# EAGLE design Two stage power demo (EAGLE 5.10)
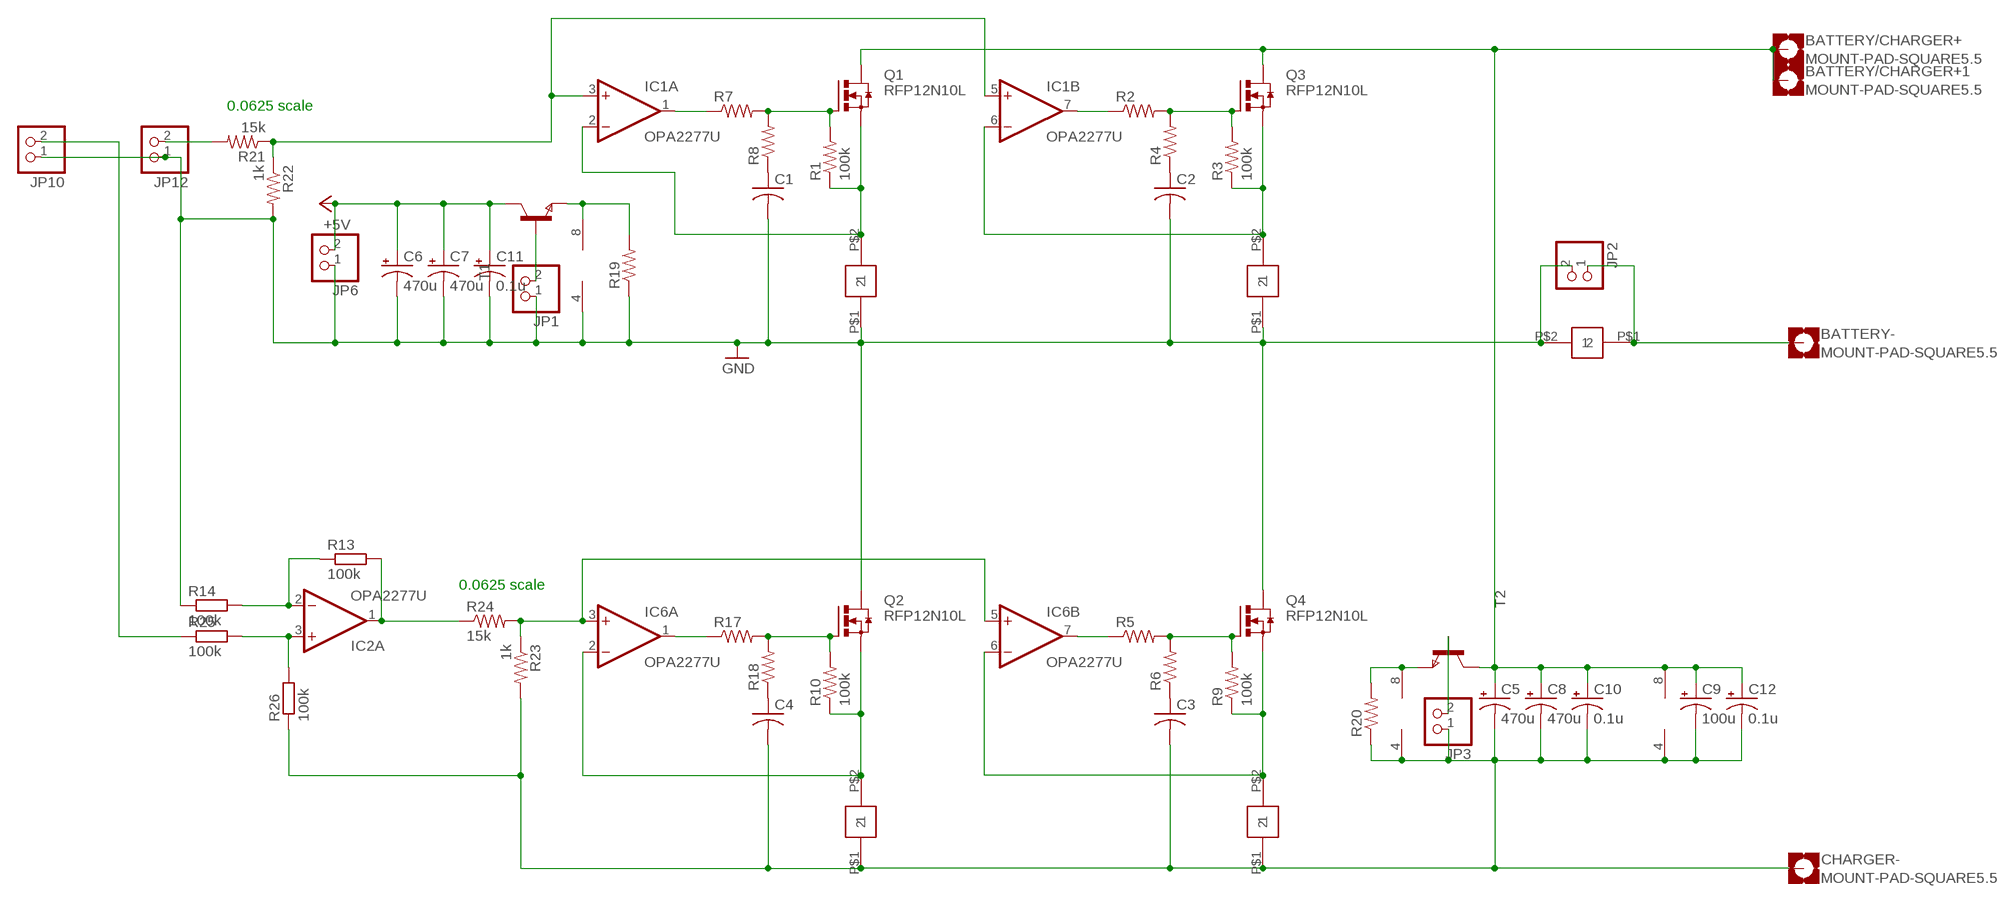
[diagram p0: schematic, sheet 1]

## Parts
1  630HR050E  [630HR050E]
BATTERY-  MOUNT-PAD-SQUARE5.5  [5,5-PAD-SQUARE]
BATTERY/CHARGER+  MOUNT-PAD-SQUARE5.5  [5,5-PAD-SQUARE]
BATTERY/CHARGER+1  MOUNT-PAD-SQUARE5.5  [5,5-PAD-SQUARE]
C1  C-US150-054X183  [C150-054X183]
C2  C-US150-054X183  [C150-054X183]
C3  C-US150-054X183  [C150-054X183]
C4  C-US150-054X183  [C150-054X183]
C5  470u  CPOL-USE5-10.5  [E5-10,5]
C6  470u  CPOL-USE5-10.5  [E5-10,5]
C7  470u  CPOL-USE5-10.5  [E5-10,5]
C8  470u  CPOL-USE5-10.5  [E5-10,5]
C9  100u  CPOL-USE2.5-7  [E2,5-7]
C10  0.1u  CPOL-USE2-4  [E2-4]
C11  0.1u  CPOL-USE2-4  [E2-4]
C12  0.1u  CPOL-USE2-4  [E2-4]
CHARGER-  MOUNT-PAD-SQUARE5.5  [5,5-PAD-SQUARE]
IC1  OPA2277U  [SO08]
IC2  OPA2277U  [SO08]
IC6  OPA2277U  [SO08]
JP1  PINHD-1X2  [1X02]
JP2  PINHD-1X2  [1X02]
JP3  PINHD-1X2  [1X02]
JP6  PINHD-1X2  [1X02]
JP10  PINHD-1X2  [1X02]
JP12  PINHD-1X2  [1X02]
Q1  RFP12N10L  [TO220-W/657-20ABP]
Q2  RFP12N10L  [TO220-W/657-20ABP]
Q3  RFP12N10L  [TO220-W/657-20ABP]
Q4  RFP12N10L  [TO220-W/657-20ABP]
R1  100k  R-US_0411/12  [0411/12]
R2  R-US_0411/12  [0411/12]
R3  100k  R-US_0411/12  [0411/12]
R4  R-US_0411/12  [0411/12]
R5  R-US_0411/12  [0411/12]
R6  R-US_0411/12  [0411/12]
R7  R-US_0411/12  [0411/12]
R8  R-US_0411/12  [0411/12]
R9  100k  R-US_0411/12  [0411/12]
R10  100k  R-US_0411/12  [0411/12]
R13  100k  R-EU_R0805  [R0805]
R14  100k  R-EU_R0805  [R0805]
R17  R-US_0411/12  [0411/12]
R18  R-US_0411/12  [0411/12]
R19  R-US_0411/12  [0411/12]
R20  R-US_0411/12  [0411/12]
R21  15k  R-US_0411/12  [0411/12]
R22  1k  R-US_0411/12  [0411/12]
R23  1k  R-US_0411/12  [0411/12]
R24  15k  R-US_0411/12  [0411/12]
R25  100k  R-EU_R0805  [R0805]
R26  100k  R-EU_R0805  [R0805]
T1  NPNSOT323  [SOT323]
T2  NPNSOT323  [SOT323]
U$2  630HR050E  [630HR050E]
U$3  630HR050E  [630HR050E]
U$4  630HR050E  [630HR050E]
U$5  630HR050E  [630HR050E]

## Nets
+5V: C6.+ C7.+ C11.+ JP6.2 T1.1(C)
GND: 1.P$1 C1.2 C2.2 C6.- C7.- C11.- IC1.4(P:V-) JP1.1 JP2.2 JP6.1 JP10.1 JP12.1 Q2.2(D) Q4.2(D) R14.1 R19.1 R22.2 U$2.P$2 U$4.P$1
LOAD: BATTERY/CHARGER+1.B5,5(MOUNT) BATTERY/CHARGER+.B5,5(MOUNT) C5.+ C8.+ C9.+ C10.+ C12.+ IC2.8(P:V+) Q1.2(D) Q3.2(D) T2.1(C)
N$1: IC1.7(B:OUT) R2.1
N$2: IC6.2(A:-IN) Q2.3(S) R10.1 U$3.P$2
N$3: C3.2 C4.2 C5.- C8.- C9.- C10.- C12.- CHARGER-.B5,5(MOUNT) IC2.4(P:V-) IC6.4(P:V-) JP3.1 R20.1 R23.2 R26.1 U$3.P$1 U$5.P$1
N$4: IC2.2(A:-IN) R13.1 R14.2
N$5: BATTERY-.B5,5(MOUNT) JP2.1 U$2.P$1
N$6: IC1.8(P:V+) R19.2 T1.3(E)
N$7: JP1.2 T1.2(B)
N$8: IC2.1(A:OUT) R13.2 R24.1
N$9: IC1.6(B:-IN) Q3.3(S) R3.1 U$4.P$2
N$10: Q1.1(G) R1.2 R7.2 R8.2
N$11: IC1.3(A:+IN) IC1.5(B:+IN) R21.1 R22.1
N$12: IC6.6(B:-IN) Q4.3(S) R9.1 U$5.P$2
N$13: C1.1 R8.1
N$14: Q3.1(G) R2.2 R3.2 R4.2
N$15: C2.1 R4.1
N$16: Q4.1(G) R5.2 R6.2 R9.2
N$18: C3.1 R6.1
N$19: IC2.3(A:+IN) R25.2 R26.2
N$20: Q2.1(G) R10.2 R17.2 R18.2
N$21: 1.P$2 IC1.2(A:-IN) Q1.3(S) R1.1
N$22: C4.1 R18.1
N$23: IC1.1(A:OUT) R7.1
N$25: IC6.7(B:OUT) R5.1
N$26: IC6.1(A:OUT) R17.1
N$27: JP12.2 R21.2
N$28: JP10.2 R25.1
N$29: IC6.8(P:V+) R20.2 T2.3(E)
N$30: IC6.3(A:+IN) IC6.5(B:+IN) R23.1 R24.2
N$32: JP3.2 T2.2(B)
Unconnected: IC2.5(B:+IN) IC2.6(B:-IN) IC2.7(B:OUT)

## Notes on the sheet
- 0.0625 scale
- 0.0625 scale

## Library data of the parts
1 U$2-U$5 = NEWPARTS:630HR050E
BATTERY- BATTERY/CHARGER+ BATTERY/CHARGER+1 CHARGER- = holes:MOUNT-PAD-SQUARE: MOUNTING PAD, square
C1-C4 = rcl:C-US: CAPACITOR, American symbol
C5-C12 = rcl:CPOL-US: POLARIZED CAPACITOR, American symbol
IC1 IC2 IC6 = linear:OPA2277: High Precision OPERATIONAL AMPLIFIERS REPLACES OP-07, OP-77, OP-177 Source: opa277.pdf
JP1-JP3 JP6 JP10 JP12 = pinhead:PINHD-1X2: PIN HEADER
Q1-Q4 = NEWPARTS:RFP12N10L: N-Channel Power MOSFET 100V; 12A; 0,2Ohm< Logic Level
R1-R10 R17-R24 = rcl:R-US_: RESISTOR, American symbol
R13 R14 R25 R26 = rcl:R-EU_: RESISTOR, European symbol
T1 T2 = zetex:NPNSOT323: NPN TRANSISTOR

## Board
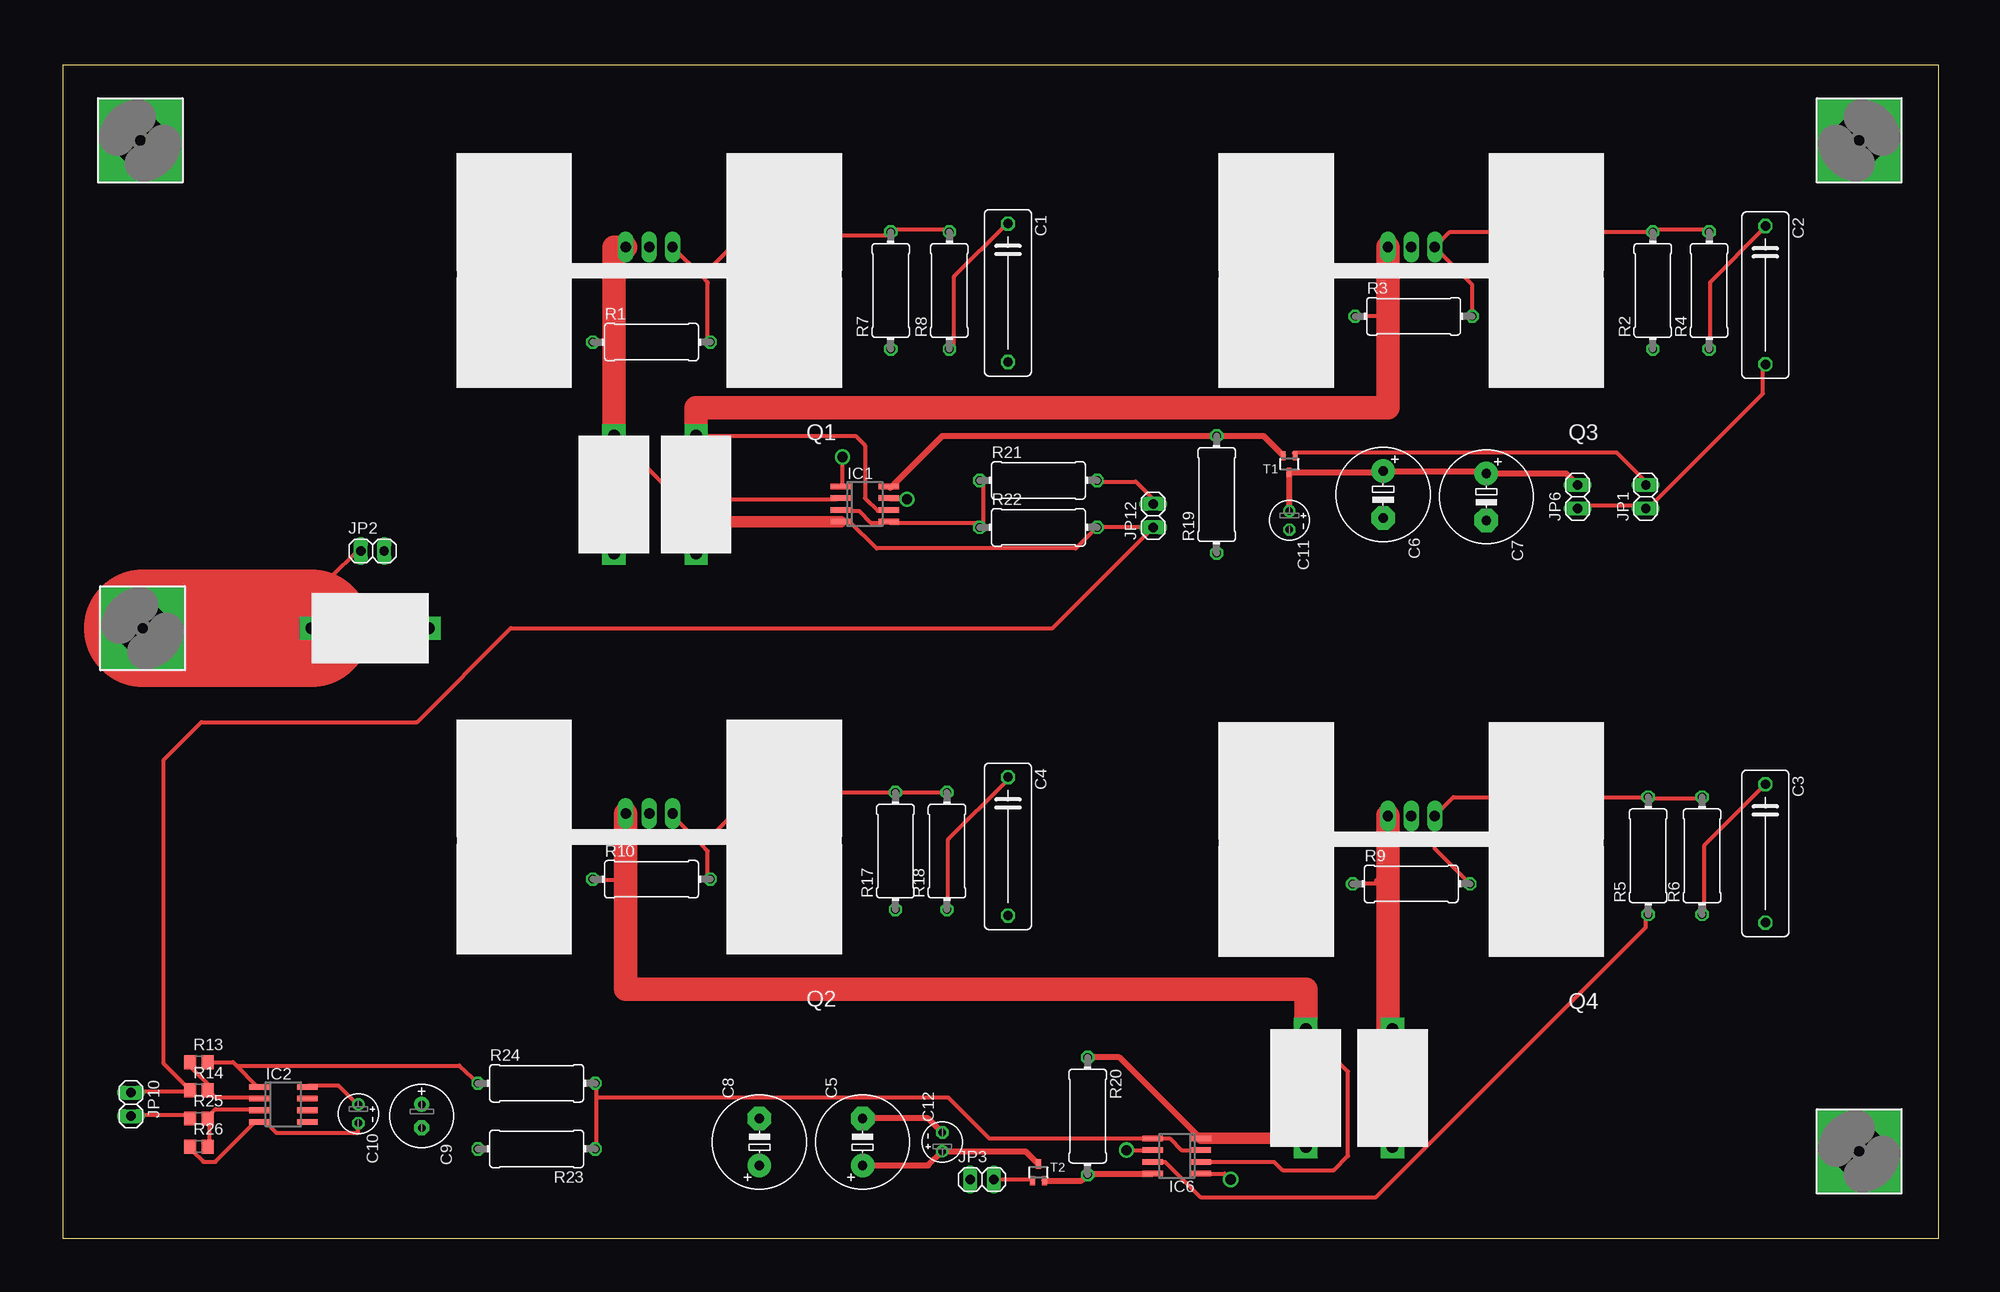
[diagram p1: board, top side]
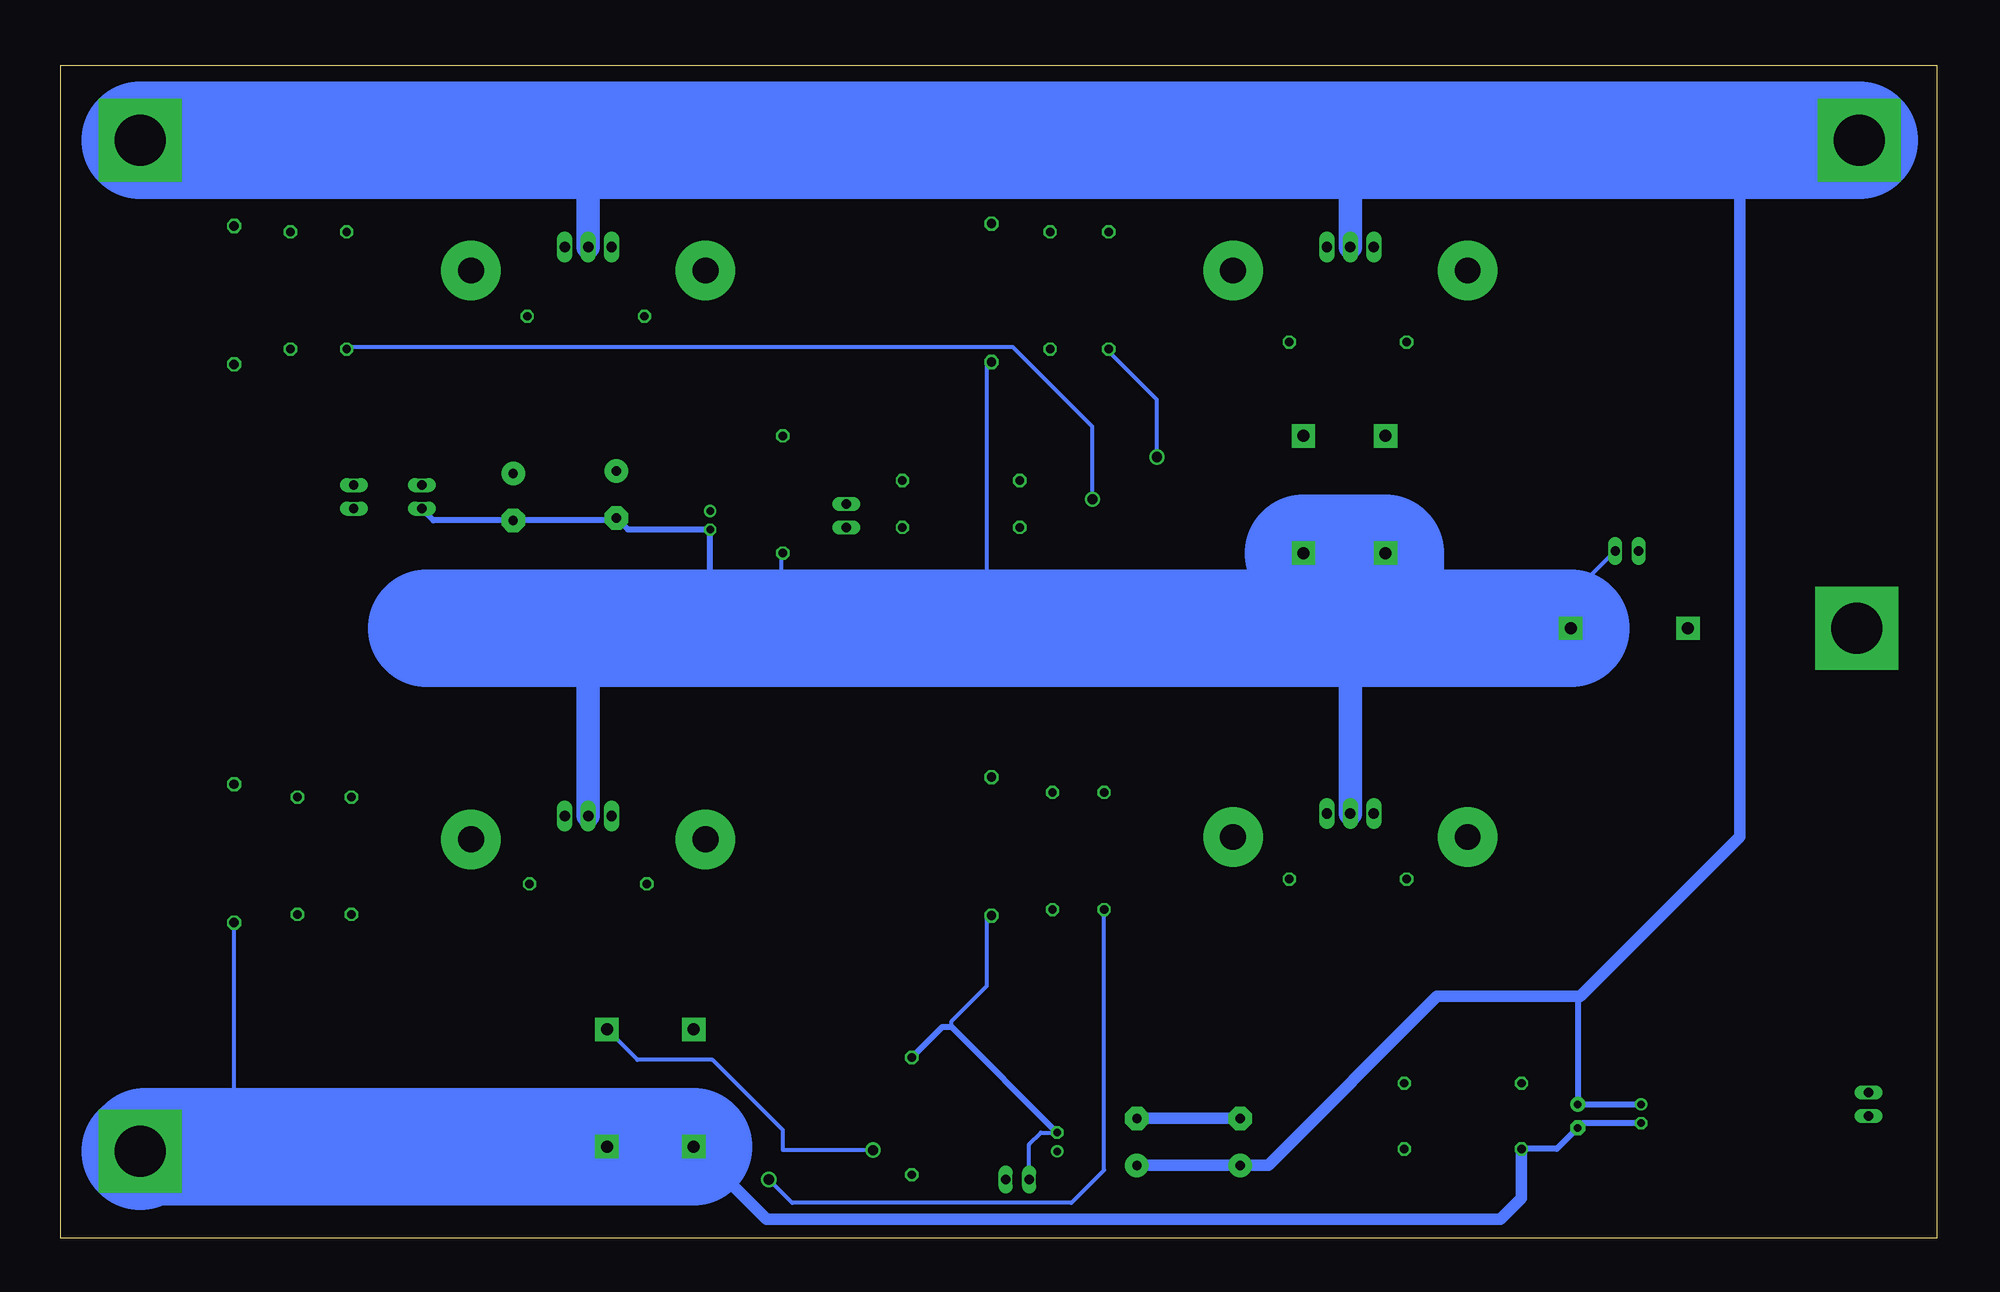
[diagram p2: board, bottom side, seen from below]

Size 203.2 x 127 mm. Coordinates in mm from the lower left corner, seen from the top.
Outline: 0,0 203.2,0 203.2,127 0,127 0,0
Copper layers (1*16): Top 0.035mm / dielectric 1.5mm / Bottom 0.035mm
Design rules "default *": minimum track width 16mil, minimum drill 24mil, track to track 8mil, track to pad 8mil, pad to pad 8mil, via to via 8mil, smd to smd 8mil, copper to edge 40mil, drill to drill 8mil, minimum pad ring 10mil, minimum via ring 8mil, stop-mask expansion 4mil, vias tented up to drill 0mil, thermal gap 10mil

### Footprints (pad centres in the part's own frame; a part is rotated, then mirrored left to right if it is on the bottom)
630HR050E = drill 1.3 pad 2.54 square: P$1 -6.35,0; P$2 6.35,0
5,5-PAD-SQUARE = drill 5.5 pad 9 square: B5,5 0,0
C150-054X183 = drill 1.016 octagon: 1 -7.493,0; 2 7.493,0
E5-10,5 = drill 1.016 pad 2.54 round: + -2.54,0 | drill 1.016 pad 2.54 octagon: - 2.54,0
E2,5-7 = drill 0.813 pad 1.6 round: + -1.27,0 | drill 0.813 pad 1.6 octagon: - 1.27,0
E2-4 = drill 0.813 pad 1.27 round: + -1.016,0 | drill 0.813 pad 1.27 octagon: - 1.016,0
SO08 = smd 0.6 x 2.2: 1 -1.905,-2.6; 2 -0.635,-2.6; 3 0.635,-2.6; 4 1.905,-2.6; 5 1.905,2.6; 6 0.635,2.6; 7 -0.635,2.6; 8 -1.905,2.6
1X02 = drill 1.016 long: 1 -1.27,0; 2 1.27,0
TO220-W/657-20ABP = drill 1.118 long: 1 -2.54,-2.54; 2 0,-2.54; 3 2.54,-2.54 | drill 2.8 pad 6.452 round: P$1 -12.7,0; P$2 12.7,0
0411/12 = drill 0.914 octagon: 1 -6.35,0; 2 6.35,0
R0805 = smd 1.3 x 1.5: 1 -0.95,0; 2 0.95,0
SOT323 = smd 0.5 x 1: 1 0,0.9; 2 -0.65,-0.9; 3 0.65,-0.9

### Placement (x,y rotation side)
1  59.69,80.52 90 top
BATTERY-  8.64,66.04 90 top
BATTERY/CHARGER+  8.38,118.87 90 top
BATTERY/CHARGER+1  194.56,118.87 0 top
C1  102.36,102.36 270 top
C2  184.4,102.11 270 top
C3  184.4,41.66 270 top
C4  102.36,42.42 270 top
C5  86.61,10.41 90 top
C6  143,80.52 270 top
C7  154.18,80.26 270 top
C8  75.44,10.41 90 top
C9  38.86,13.21 270 top
C10  32,13.46 270 top
C11  132.84,77.72 270 top
C12  95.25,10.41 90 top
CHARGER-  194.56,9.4 90 top
IC1  86.87,79.5 270 top
IC2  23.88,14.48 270 top
IC6  120.65,8.89 90 top
JP1  171.45,80.26 90 top
JP2  33.53,74.42 0 top
JP3  99.57,6.35 0 top
JP6  164.08,80.26 90 top
JP10  7.37,14.48 270 top
JP12  118.11,78.23 90 top
Q1  63.5,104.78 180 top
Q2  63.5,43.43 180 top
Q3  146.05,104.78 180 top
Q4  146.05,43.18 180 top
R1  63.75,97.03 0 top
R2  172.21,102.62 90 top
R3  146.3,99.82 0 top
R4  178.31,102.62 90 top
R5  171.7,41.4 90 top
R6  177.55,41.4 90 top
R7  89.66,102.62 90 top
R8  96.01,102.62 90 top
R9  146.05,38.35 0 top
R10  63.75,38.86 0 top
R13  14.73,19.05 0 top
R14  14.73,16 0 top
R17  90.17,41.91 90 top
R18  95.76,41.91 90 top
R19  124.97,80.52 90 top
R20  111,13.21 270 top
R21  105.66,82.04 0 top
R22  105.66,76.96 0 top
R23  51.31,9.65 180 top
R24  51.31,16.76 0 top
R25  14.73,12.95 0 top
R26  14.73,9.91 0 top
T1  132.84,83.82 180 top
T2  105.66,7.11 0 top
U$2  33.27,66.04 0 top
U$3  134.62,16.26 90 top
U$4  68.58,80.52 90 top
U$5  144.02,16.26 90 top

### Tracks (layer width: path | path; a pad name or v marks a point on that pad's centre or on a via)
+5V
  Top 0.406: T1.1 132.72,83.19
  Top 0.635: C11.+ T1.1 142.86,82.92 C6.+ 153.92,83.06 C7.+ 162.81,82.8 JP6.2
GND
  Top 0.406: JP6.1 164.47,79.38 171.45,79.38 JP1.1 171.45,78.74 184.15,91.44 184.15,94.61 C2.2 | JP10.1 7.62,15.88 13.34,15.88 R14.1 10.92,18.86 10.92,51.82 14.99,55.88 38.35,55.88 48.51,66.04 107.19,66.04 JP12.1 R22.2 109.73,74.68 88.14,74.68 85.22,77.6 IC1.4
  Top 1.27: U$4.P$1 72.01,77.6 IC1.4
  Bottom 0.406: R19.1 125.09,73.66 125.09,66.04 | JP2.2 37.47,71.75 U$2.P$2 | C1.2 102.87,94.61 102.87,66.04 | 163.58,66.04 164.47,71.75
  Bottom 0.635: JP6.1 162.81,77.72 C7.- 143.26,77.72 C6.- 141.73,76.71 C11.- 132.84,71.75 164.47,71.75
  Bottom 12.7: 59.69,66.04 U$2.P$2 | U$4.P$1 1.P$1 59.69,66.04 | 59.69,66.04 63.25,66.04 102.87,66.04 125.09,66.04 154.31,66.04 163.58,66.04
  Bottom 2.54: 154.31,66.04 146.05,66.04 Q4.2 | Q2.2 63.5,66.55 63.25,66.55 63.25,66.04
LOAD
  Top 0.406: IC2.8 26.67,16.51 29.84,16.51 31.75,14.61 C10.+
  Top 0.635: C5.+ 93.73,7.87 C12.+ 104.28,9.4 T2.1
  Bottom 0.406: C10.+ 31.75,14.61
  Bottom 0.635: 39.12,26.16 38.86,25.91 C9.+ C10.+
  Bottom 1.27: 21.08,118.87 21.34,118.62 21.34,43.43 38.61,26.16 39.12,26.16 54.1,26.16 72.39,7.87 C8.+ C5.+
  Bottom 12.7: BATTERY/CHARGER+1.B5,5 145.8,118.87 63.5,118.87 21.08,118.87 BATTERY/CHARGER+.B5,5
  Bottom 2.54: 63.5,118.87 Q1.2 | Q3.2 146.05,123.95 145.8,123.95 145.8,118.87
N$1  (via drill 1.1)
  Top 0.406: v91.44,80.01 89.53,80.01 IC1.7
  Bottom 0.406: R2.1 172.09,96.52 100.08,96.52 91.44,87.88 v91.44,80.01
N$2
  Top 0.406: R10.1 57.78,38.73 60.96,38.73 | IC6.2 131.19,8.26 132.08,7.37 137.67,7.37 139.19,8.89 139.19,18.03 U$3.P$2
  Top 2.54: U$3.P$2 134.62,26.92 60.96,26.92 60.96,38.73 Q2.3
N$3
  Top 0.406: R26.1 13.97,9.53 15.24,8.26 16.51,8.26 20.95,12.7 IC2.4 21.59,12.7 21.84,12.7 23.11,11.43 32,11.43 C10.- | IC6.4 123.19,10.79
  Top 0.635: 123.19,10.79 114.43,19.56 R20.1 | C12.- 93.73,12.95 C5.-
  Top 1.27: IC6.4 133.73,10.79 U$3.P$1
  Bottom 0.406: C4.2 102.87,34.92 102.87,27.3 106.68,23.5 106.68,22.86 | C3.2 184.4,10.67 185.17,9.91 | JP3.1 98.3,10.16 97.03,11.43 C12.-
  Bottom 0.635: C10.- 38.35,12.45 C9.- 41.15,9.65 R23.2 | C12.- 106.68,22.86 107.7,22.86 R20.1
  Bottom 1.27: C5.- C8.- | R23.2 44.96,4.32 47.24,2.03 126.75,2.03 U$3.P$1
  Bottom 12.7: U$3.P$1 U$5.P$1 185.17,9.91 194.06,9.91 CHARGER-.B5,5
N$4
  Top 0.406: R13.1 13.97,19.05 13.97,18.41 15.88,16.51 R14.2 15.88,15.88 16.51,15.24 20.95,15.24 IC2.2
N$5
  Top 0.406: JP2.1 31.75,74.3 29.21,71.75 U$2.P$1
  Top 12.7: BATTERY-.B5,5 U$2.P$1
N$6
  Top 0.406: IC1.8 89.53,81.28 | 124.46,87 R19.2
  Top 0.635: 89.53,81.28 89.66,81.28 95.25,86.87 124.33,86.87 124.46,87 | R19.2 130.04,86.87 T1.3
N$7
  Top 0.406: T1.2 133.35,85.09 168.28,85.09 171.45,81.92 JP1.2
N$8
  Top 0.406: 18.8,18.67 20.95,16.51 IC2.1 | 18.8,18.67 18.41,19.05 R13.2 | 18.8,18.67 42.93,18.67 R24.1
N$9
  Top 0.406: IC1.6 88.9,78.74 88.27,78.74 86.87,80.14 86.87,85.85 85.85,86.87 U$4.P$2 | 143.51,99.82 R3.1
  Top 2.54: U$4.P$2 68.58,89.92 143.51,89.92 143.51,99.82 Q3.3
N$10
  Top 0.406: R8.2 95.89,109.22 90.17,109.22 R7.2 89.53,108.58 73.66,108.58 69.22,104.14 | 69.22,104.14 Q1.1 | 69.22,104.14 69.85,103.5 69.85,97.16 R1.2
N$11
  Top 0.406: IC1.3 84.45,78.74 86.23,78.74 87.5,77.47 88.9,77.47 IC1.5 89.53,77.47 99.06,77.47 R22.1 99.69,77.47 99.69,81.92 R21.1
N$12  (via drill 1.1)
  Top 0.406: v115.19,9.53 IC6.6 | 143.51,38.73 142.75,38.73 | 142.75,38.73 142.24,38.73 | R9.1 142.37,38.35 142.75,38.73
  Top 2.54: Q4.3 143.51,38.73 143.51,22.61 U$5.P$2
  Bottom 0.406: v115.19,9.53 124.97,9.53 124.97,11.68 132.59,19.3 140.72,19.3 U$5.P$2
N$13
  Top 0.406: R8.1 96.52,96.52 96.52,104.14 102.23,109.86 C1.1
N$14
  Top 0.406: R4.2 177.8,109.22 172.72,109.22 R2.2 150.24,108.97 Q3.1 152.65,103.25 R3.2
N$15
  Top 0.406: R4.1 178.44,96.52 178.44,103.5 184.15,109.22 C2.1
N$16
  Top 0.406: R6.2 177.16,47.62 172.09,47.62 R5.2 150.62,47.75 Q4.1 148.59,42.16 R9.2
N$18
  Top 0.406: R6.1 177.8,35.56 177.8,42.55 C3.1
N$19
  Top 0.406: R26.2 15.88,10.16 15.88,12.7 R25.2 15.88,13.34 16.51,13.97 20.95,13.97 IC2.3
N$20
  Top 0.406: R18.2 R17.2 74.93,48.26 69.22,42.55 | 69.22,42.55 66.04,45.72 Q2.1 | 69.22,42.55 69.85,41.91 69.85,39.37 R10.2
N$21
  Top 0.406: IC1.2 83.82,80.01 66.67,80.01 60.33,86.36 1.P$2 | R1.1 57.78,97.16 59.69,97.16
  Top 2.54: Q1.3 59.69,107.31 59.69,97.16 1.P$2
N$22
  Top 0.406: R18.1 95.89,35.56 95.89,43.18 102.23,49.53 C4.1
N$23  (via drill 1.1)
  Top 0.406: v84.45,84.58 84.45,81.28 IC1.1
  Bottom 0.406: v84.45,84.58 84.45,90.81 89.53,95.89 R7.1
N$25
  Top 0.406: IC6.7 119.38,8.26 123.19,4.45 142.24,4.45 171.45,33.66 171.45,34.92 R5.1
N$26  (via drill 1.1)
  Top 0.406: IC6.1 125.86,6.99 v126.49,6.35
  Bottom 0.406: R17.1 90.17,7.37 93.73,3.81 123.95,3.81 v126.49,6.35
N$27
  Top 0.406: R21.2 112.39,81.92 116.2,81.92 118.11,80.01 JP12.2
N$28
  Top 0.406: R25.1 13.34,13.34 7.62,13.34 JP10.2
N$29
  Top 0.406: R20.2 111.12,6.99
  Top 0.635: 111.12,6.99 IC6.8 | T2.3 110.35,6.21 R20.2
N$30
  Top 0.406: IC6.3 121.16,9.53 119.89,10.79 IC6.5 100.33,10.79 95.89,15.24 57.78,15.24 | 57.78,15.24 57.78,16.51 R24.2 | 57.78,15.24 57.78,10.16 R23.1
N$32
  Top 0.406: JP3.2 104.88,6.35 T2.2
